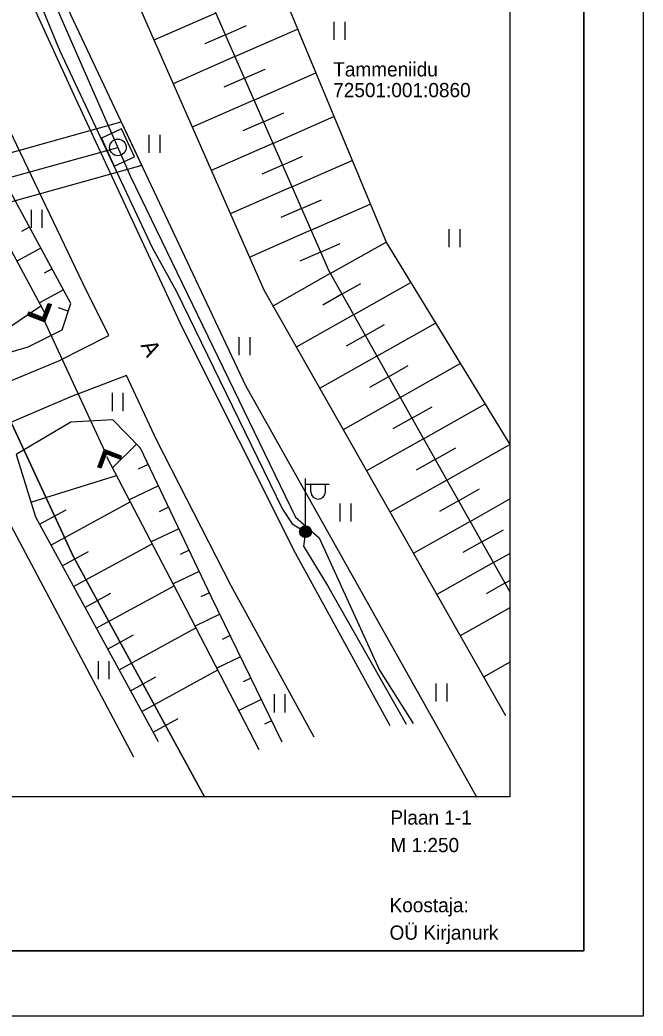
# Model space of a CAD drawing. Extents: x 533290.5 to 533343, y 6581488.2 to 6581562.4.
# Drawn here: x 533316.74 to 533343.03, y 6581488.17 to 6581530.19 of the extents above; entities that cross this region are included whole.
import ezdxf

# ---------------------------------------------------------------- set-up
doc = ezdxf.new("R2010")
doc.units = 0
for name, color, linetype in [('HALJASTUS', 7, 'Continuous'), ('KASUTUSALA', 7, 'Continuous'), ('MPKAABEL', 7, 'Continuous'), ('PIIR', 7, 'Continuous'), ('POST', 7, 'Continuous'), ('PR_SIDE', 7, 'Continuous'), ('RELJEEF', 7, 'Continuous'), ('SITRASS', 7, 'Continuous'), ('TEE', 7, 'Continuous'), ('TRUUP', 7, 'Continuous'), ('VORMISTUS', 7, 'Continuous')]:
    doc.layers.add(name, color=color, linetype=linetype)

msp = doc.modelspace()

# ---------------------------------------------------------------- linework, layer by layer
at = {"layer": 'HALJASTUS'}
for p, q in [((533329.989, 6581530.114), (533329.989, 6581529.353)), ((533330.444, 6581530.114), (533330.444, 6581529.353)), ((533322.182, 6581525.342), (533322.182, 6581524.581)), ((533322.637, 6581525.342), (533322.637, 6581524.581)), ((533317.213, 6581522.185), (533317.213, 6581521.424)), ((533317.668, 6581522.185), (533317.668, 6581521.424)), ((533334.841, 6581521.373), (533334.841, 6581520.611)), ((533335.297, 6581521.373), (533335.297, 6581520.611)), ((533325.98, 6581516.812), (533325.98, 6581516.051)), ((533326.435, 6581516.812), (533326.435, 6581516.051)), ((533320.631, 6581514.458), (533320.631, 6581513.697)), ((533321.086, 6581514.458), (533321.086, 6581513.697)), ((533330.242, 6581509.802), (533330.242, 6581509.041)), ((533330.697, 6581509.802), (533330.697, 6581509.041)), ((533320.04, 6581503.14), (533320.04, 6581502.379)), ((533320.495, 6581503.14), (533320.495, 6581502.379)), ((533334.293, 6581502.201), (533334.293, 6581501.44)), ((533334.748, 6581502.201), (533334.748, 6581501.44)), ((533327.467, 6581501.747), (533327.467, 6581500.986)), ((533327.922, 6581501.747), (533327.922, 6581500.986))]:
    msp.add_line(p, q, dxfattribs=at)
at = {"layer": 'KASUTUSALA'}
msp.add_lwpolyline([(533320.604, 6581525.778), (533321.014, 6581525.892), (533321.88, 6581524.058), (533312.538, 6581521.458), (533311.685, 6581523.295)], close=True, dxfattribs=at)
at = {"layer": 'MPKAABEL'}
msp.add_lwpolyline([(533309.585, 6581549.925), (533311.184, 6581545.697), (533315.768, 6581535.104), (533317.532, 6581531.021), (533318.413, 6581528.914), (533322.317, 6581520.59), (533323.335, 6581518.773), (533327.821, 6581509.555), (533328.223, 6581508.944), (533328.79, 6581508.605), (533328.705, 6581507.998), (533329.72, 6581506.331), (533333.034, 6581500.482)], dxfattribs=at)
at = {"layer": 'PIIR'}
for points in [[(533324.524, 6581497.425), (533319, 6581507.54), (533311.52, 6581523.65), (533301.8, 6581547.63), (533300.925, 6581549.925)], [(533300.925, 6581549.925), (533301.8, 6581547.63), (533311.52, 6581523.65), (533319, 6581507.54), (533324.524, 6581497.425)], [(533310.517, 6581549.925), (533314.39, 6581540.11), (533318.28, 6581531.69), (533326.26, 6581514.77), (533336.001, 6581497.425)], [(533337.407, 6581540.101), (533324.47, 6581534.41), (533318.28, 6581531.69), (533326.26, 6581514.77), (533336.001, 6581497.425)]]:
    msp.add_lwpolyline(points, dxfattribs=at)
at = {"layer": 'POST'}
for p, q in [((533328.79, 6581508.855), (533328.79, 6581510.855)), ((533328.79, 6581510.605), (533329.79, 6581510.605)), ((533329.017, 6581510.284), (533329.017, 6581510.605)), ((533329.63, 6581510.284), (533329.63, 6581510.605)), ((533328.79, 6581508.605), (533328.79, 6581508.605))]:
    msp.add_line(p, q, dxfattribs=at)
for radius in [0.25, 0.225, 0.2, 0.175, 0.15, 0.125, 0.1, 0.075, 0.05, 0.025]:
    msp.add_circle((533328.79, 6581508.605), radius, dxfattribs=at)
msp.add_arc((533329.323, 6581510.284), 0.306, 180, 0, dxfattribs=at)
at = {"layer": 'PR_SIDE'}
msp.add_line((533296.157, 6581517.936), (533320.872, 6581524.815), dxfattribs=at)
msp.add_lwpolyline([(533321.567, 6581524.419), (533321.023, 6581525.6), (533320.178, 6581525.212), (533320.722, 6581524.031)], close=True, dxfattribs=at)
msp.add_circle((533320.872, 6581524.815), 0.35, dxfattribs=at)
at = {"layer": 'RELJEEF'}
for p, q in [((533325.005, 6581530.479), (533322.395, 6581529.334)), ((533325.407, 6581529.563), (533326.296, 6581529.952)), ((533325.808, 6581528.647), (533328.457, 6581529.808)), ((533325.407, 6581529.563), (533324.537, 6581529.181)), ((533325.808, 6581528.647), (533323.199, 6581527.503)), ((533326.21, 6581527.731), (533325.34, 6581527.35)), ((533326.21, 6581527.731), (533327.086, 6581528.115)), ((533326.611, 6581526.815), (533329.223, 6581527.96)), ((533326.611, 6581526.815), (533324.004, 6581525.672)), ((533327.013, 6581525.899), (533327.877, 6581526.278)), ((533327.414, 6581524.983), (533329.99, 6581526.113)), ((533327.013, 6581525.899), (533326.144, 6581525.519)), ((533327.414, 6581524.983), (533324.809, 6581523.841)), ((533327.816, 6581524.068), (533328.668, 6581524.441)), ((533327.816, 6581524.068), (533326.947, 6581523.687)), ((533328.217, 6581523.152), (533330.757, 6581524.265)), ((533328.217, 6581523.152), (533325.613, 6581522.01)), ((533328.618, 6581522.236), (533327.751, 6581521.856)), ((533328.618, 6581522.236), (533329.459, 6581522.604)), ((533329.02, 6581521.32), (533331.523, 6581522.417)), ((533317.143, 6581521.447), (533316.807, 6581521.264)), ((533329.02, 6581521.32), (533326.418, 6581520.179)), ((533317.62, 6581520.568), (533316.61, 6581520.019)), ((533329.421, 6581520.404), (533330.25, 6581520.767)), ((533329.835, 6581519.494), (533332.186, 6581520.821)), ((533329.421, 6581520.404), (533328.554, 6581520.024)), ((533318.097, 6581519.689), (533317.759, 6581519.505)), ((533329.835, 6581519.494), (533327.408, 6581518.125)), ((533330.326, 6581518.623), (533331.119, 6581519.07)), ((533330.818, 6581517.752), (533333.226, 6581519.111)), ((533318.574, 6581518.81), (533317.558, 6581518.259)), ((533330.326, 6581518.623), (533329.518, 6581518.167)), ((533314.825, 6581516.252), (533317.623, 6581518.137)), ((533318.778, 6581517.906), (533318.362, 6581518.042)), ((533330.818, 6581517.752), (533328.396, 6581516.386)), ((533331.309, 6581516.881), (533332.122, 6581517.34)), ((533331.8, 6581516.01), (533334.271, 6581517.404)), ((533331.309, 6581516.881), (533330.503, 6581516.426)), ((533331.8, 6581516.01), (533329.384, 6581514.647)), ((533332.292, 6581515.139), (533333.126, 6581515.61)), ((533332.783, 6581514.268), (533335.316, 6581515.698)), ((533332.292, 6581515.139), (533331.487, 6581514.686)), ((533332.783, 6581514.268), (533330.372, 6581512.908)), ((533333.274, 6581513.398), (533334.129, 6581513.88)), ((533333.766, 6581512.527), (533336.361, 6581513.991)), ((533333.274, 6581513.398), (533332.472, 6581512.945)), ((533321.661, 6581512.301), (533320.644, 6581511.304)), ((533333.766, 6581512.527), (533331.36, 6581511.169)), ((533334.748, 6581510.785), (533337.406, 6581512.284)), ((533334.257, 6581511.656), (533335.133, 6581512.15)), ((533322.154, 6581511.442), (533321.732, 6581511.241)), ((533334.257, 6581511.656), (533333.456, 6581511.204)), ((533317.202, 6581509.848), (533320.818, 6581510.97)), ((533322.584, 6581510.54), (533321.35, 6581509.952)), ((533334.748, 6581510.785), (533332.348, 6581509.43)), ((533335.24, 6581509.914), (533336.136, 6581510.419)), ((533318.043, 6581508.043), (533321.391, 6581509.872)), ((533323.014, 6581509.637), (533322.613, 6581509.446)), ((533335.24, 6581509.914), (533334.441, 6581509.463)), ((533335.731, 6581509.043), (533337.407, 6581509.988)), ((533317.564, 6581508.921), (533318.685, 6581509.534)), ((533335.731, 6581509.043), (533333.336, 6581507.691)), ((533323.443, 6581508.734), (533322.276, 6581508.178)), ((533336.223, 6581508.172), (533337.14, 6581508.689)), ((533319.002, 6581506.288), (533322.317, 6581508.099)), ((533336.223, 6581508.172), (533335.425, 6581507.722)), ((533318.523, 6581507.166), (533319.633, 6581507.772)), ((533323.873, 6581507.831), (533323.495, 6581507.651)), ((533336.714, 6581507.301), (533337.407, 6581507.692)), ((533336.714, 6581507.301), (533334.324, 6581505.953)), ((533324.303, 6581506.928), (533323.202, 6581506.404)), ((533319.961, 6581504.533), (533323.242, 6581506.326)), ((533337.205, 6581506.43), (533336.409, 6581505.981)), ((533337.205, 6581506.43), (533337.407, 6581506.544)), ((533319.482, 6581505.411), (533320.581, 6581506.011)), ((533324.733, 6581506.025), (533324.377, 6581505.855)), ((533325.169, 6581505.125), (533324.131, 6581504.619)), ((533337.407, 6581505.396), (533335.312, 6581504.214)), ((533320.44, 6581503.655), (533321.529, 6581504.25)), ((533320.92, 6581502.778), (533324.166, 6581504.551)), ((533325.607, 6581504.226), (533325.269, 6581504.061)), ((533337.407, 6581504.247), (533337.394, 6581504.24)), ((533326.046, 6581503.327), (533325.053, 6581502.843)), ((533337.407, 6581503.099), (533336.3, 6581502.475)), ((533321.399, 6581501.9), (533322.475, 6581502.488)), ((533321.879, 6581501.023), (533325.088, 6581502.776)), ((533326.484, 6581502.429), (533326.161, 6581502.271)), ((533326.922, 6581501.53), (533325.975, 6581501.068)), ((533322.358, 6581500.145), (533323.422, 6581500.726)), ((533327.36, 6581500.631), (533327.052, 6581500.481))]:
    msp.add_line(p, q, dxfattribs=at)
for points in [[(533313.894, 6581549.925), (533319.924, 6581534.957), (533327.024, 6581518.802), (533337.222, 6581500.851)], [(533317.44, 6581549.925), (533322.824, 6581535.454), (533329.77, 6581519.61), (533337.407, 6581506.072)], [(533320.813, 6581549.925), (533325.642, 6581536.592), (533332.201, 6581520.786), (533337.407, 6581512.283)], [(533301.723, 6581543.178), (533305.883, 6581533.554), (533310.992, 6581522.492), (533312.743, 6581519.341), (533315.111, 6581515.828), (533317.088, 6581516.41), (533318.52, 6581517.115), (533318.885, 6581518.236), (533315.236, 6581524.96), (533309.937, 6581536.665), (533305.583, 6581547.162)], [(533317.816, 6581517.779), (533314.186, 6581524.519), (533308.956, 6581536.213), (533304.785, 6581546.815)], [(533327.799, 6581499.732), (533324.818, 6581505.846), (533321.825, 6581512.134), (533320.659, 6581513.322), (533318.883, 6581513.228), (533316.576, 6581511.865), (533317.392, 6581509.235), (533322.569, 6581499.759)], [(533326.836, 6581499.41), (533323.749, 6581505.354), (533320.405, 6581511.761)]]:
    msp.add_lwpolyline(points, dxfattribs=at)
at = {"layer": 'SITRASS'}
msp.add_lwpolyline([(533310.167, 6581549.925), (533314.701, 6581538.877), (533321.41, 6581523.582), (533328.373, 6581509.225), (533329.36, 6581508.341), (533331.911, 6581502.769), (533333.333, 6581500.509)], dxfattribs=at)
at = {"layer": 'TEE'}
for points in [[(533332.365, 6581500.423), (533328.37, 6581507.695), (533323.599, 6581517.205), (533319.091, 6581526.86), (533313.759, 6581538.502), (533308.885, 6581549.596)], [(533300.834, 6581542.715), (533304.915, 6581533.103), (533309.953, 6581521.952), (533312.545, 6581516.498), (533313.78, 6581513.945), (533314.812, 6581514.331), (533318.385, 6581515.808), (533320.487, 6581516.887), (533319.399, 6581519.093), (533316.302, 6581525.558), (533311.019, 6581537.113), (533306.407, 6581547.637)], [(533329.158, 6581499.94), (533325.649, 6581506.325), (533322.502, 6581512.484), (533321.231, 6581515.194), (533318.912, 6581514.304), (533315.616, 6581512.897), (533314.671, 6581512.318), (533316.354, 6581508.865), (533321.528, 6581499.114)]]:
    msp.add_lwpolyline(points, dxfattribs=at)
at = {"layer": 'TRUUP'}
for p, q in [((533317.706, 6581517.646), (533317.937, 6581518.238)), ((533317.747, 6581517.554), (533318.003, 6581518.212)), ((533317.787, 6581517.461), (533318.07, 6581518.187)), ((533317.864, 6581518.05), (533317.97, 6581517.932)), ((533317.874, 6581518.077), (533317.981, 6581517.958)), ((533317.884, 6581518.103), (533317.991, 6581517.984)), ((533317.894, 6581518.129), (533318.001, 6581518.01)), ((533317.904, 6581518.155), (533318.011, 6581518.036)), ((533317.915, 6581518.181), (533318.021, 6581518.062)), ((533317.925, 6581518.207), (533318.031, 6581518.088)), ((533317.935, 6581518.233), (533318.042, 6581518.114)), ((533317.937, 6581518.238), (533318.07, 6581518.187)), ((533317.978, 6581518.222), (533318.052, 6581518.141)), ((533318.03, 6581518.202), (533318.062, 6581518.167)), ((533317.114, 6581517.877), (533317.062, 6581517.744)), ((533317.062, 6581517.744), (533317.787, 6581517.461)), ((533317.073, 6581517.771), (533317.116, 6581517.723)), ((533317.083, 6581517.797), (533317.168, 6581517.703)), ((533317.088, 6581517.81), (533317.747, 6581517.554)), ((533317.093, 6581517.823), (533317.22, 6581517.682)), ((533317.103, 6581517.85), (533317.272, 6581517.662)), ((533317.113, 6581517.876), (533317.323, 6581517.642)), ((533317.114, 6581517.877), (533317.706, 6581517.646)), ((533317.163, 6581517.857), (533317.375, 6581517.622)), ((533317.215, 6581517.837), (533317.427, 6581517.602)), ((533317.267, 6581517.817), (533317.479, 6581517.582)), ((533317.319, 6581517.797), (533317.53, 6581517.561)), ((533317.371, 6581517.776), (533317.582, 6581517.541)), ((533317.422, 6581517.756), (533317.634, 6581517.521)), ((533317.474, 6581517.736), (533317.686, 6581517.501)), ((533317.526, 6581517.716), (533317.737, 6581517.481)), ((533317.578, 6581517.696), (533317.787, 6581517.462)), ((533317.629, 6581517.676), (533317.798, 6581517.488)), ((533317.681, 6581517.655), (533317.808, 6581517.515)), ((533317.711, 6581517.659), (533317.818, 6581517.541)), ((533317.722, 6581517.685), (533317.828, 6581517.567)), ((533317.732, 6581517.711), (533317.838, 6581517.593)), ((533317.742, 6581517.737), (533317.848, 6581517.619)), ((533317.752, 6581517.764), (533317.859, 6581517.645)), ((533317.762, 6581517.79), (533317.869, 6581517.671)), ((533317.772, 6581517.816), (533317.879, 6581517.697)), ((533317.783, 6581517.842), (533317.889, 6581517.723)), ((533317.793, 6581517.868), (533317.899, 6581517.749)), ((533317.803, 6581517.894), (533317.909, 6581517.775)), ((533317.813, 6581517.92), (533317.92, 6581517.801)), ((533317.823, 6581517.946), (533317.93, 6581517.828)), ((533317.833, 6581517.972), (533317.94, 6581517.854)), ((533317.843, 6581517.998), (533317.95, 6581517.88)), ((533317.854, 6581518.024), (533317.96, 6581517.906)), ((533320.34, 6581511.979), (533317.747, 6581517.554)), ((533320.299, 6581512.071), (533320.02, 6581511.344)), ((533320.34, 6581511.979), (533320.087, 6581511.319)), ((533320.381, 6581511.887), (533320.153, 6581511.293)), ((533320.276, 6581511.612), (533320.168, 6581511.73)), ((533320.286, 6581511.638), (533320.178, 6581511.756)), ((533320.296, 6581511.664), (533320.188, 6581511.782)), ((533320.306, 6581511.69), (533320.199, 6581511.808)), ((533320.316, 6581511.717), (533320.209, 6581511.835)), ((533320.326, 6581511.743), (533320.219, 6581511.861)), ((533320.336, 6581511.769), (533320.229, 6581511.887)), ((533320.346, 6581511.795), (533320.239, 6581511.913)), ((533320.356, 6581511.821), (533320.249, 6581511.939)), ((533320.366, 6581511.847), (533320.259, 6581511.965)), ((533320.376, 6581511.873), (533320.269, 6581511.991)), ((533320.406, 6581511.877), (533320.279, 6581512.017)), ((533320.458, 6581511.857), (533320.289, 6581512.044)), ((533321.026, 6581511.791), (533320.299, 6581512.071)), ((533320.51, 6581511.837), (533320.299, 6581512.07)), ((533321, 6581511.725), (533320.34, 6581511.979)), ((533320.562, 6581511.817), (533320.349, 6581512.052)), ((533320.975, 6581511.659), (533320.381, 6581511.887)), ((533320.614, 6581511.797), (533320.401, 6581512.032)), ((533320.665, 6581511.777), (533320.453, 6581512.012)), ((533320.717, 6581511.758), (533320.505, 6581511.992)), ((533320.769, 6581511.738), (533320.557, 6581511.972)), ((533320.821, 6581511.718), (533320.608, 6581511.952)), ((533320.873, 6581511.698), (533320.66, 6581511.932)), ((533320.925, 6581511.678), (533320.712, 6581511.912)), ((533320.975, 6581511.66), (533320.764, 6581511.892)), ((533320.985, 6581511.686), (533320.816, 6581511.872)), ((533320.995, 6581511.712), (533320.868, 6581511.852)), ((533321.005, 6581511.738), (533320.92, 6581511.832)), ((533321.015, 6581511.764), (533320.971, 6581511.812)), ((533320.975, 6581511.659), (533321.026, 6581511.791)), ((533320.153, 6581511.293), (533320.02, 6581511.344)), ((533320.06, 6581511.329), (533320.028, 6581511.364)), ((533320.111, 6581511.309), (533320.038, 6581511.39)), ((533320.155, 6581511.298), (533320.048, 6581511.416)), ((533320.165, 6581511.325), (533320.058, 6581511.443)), ((533320.175, 6581511.351), (533320.068, 6581511.469)), ((533320.185, 6581511.377), (533320.078, 6581511.495)), ((533320.195, 6581511.403), (533320.088, 6581511.521)), ((533320.205, 6581511.429), (533320.098, 6581511.547)), ((533320.215, 6581511.455), (533320.108, 6581511.573)), ((533320.225, 6581511.481), (533320.118, 6581511.599)), ((533320.235, 6581511.507), (533320.128, 6581511.626)), ((533320.245, 6581511.534), (533320.138, 6581511.652)), ((533320.255, 6581511.56), (533320.148, 6581511.678)), ((533320.265, 6581511.586), (533320.158, 6581511.704))]:
    msp.add_line(p, q, dxfattribs=at)
at = {"layer": 'VORMISTUS'}
for points in [[(533290.532, 6581562.425), (533343.032, 6581562.425), (533343.032, 6581488.175), (533290.532, 6581488.175)], [(533293.032, 6581490.925), (533340.532, 6581490.925), (533340.532, 6581559.675), (533293.032, 6581559.675)], [(533293.032, 6581559.675), (533340.532, 6581559.675), (533340.532, 6581490.925), (533293.032, 6581490.925)], [(533337.407, 6581497.425), (533296.157, 6581497.425), (533296.157, 6581549.925), (533337.407, 6581549.925)]]:
    msp.add_lwpolyline(points, close=True, dxfattribs=at)

# ---------------------------------------------------------------- texts
at = {"layer": 'PIIR'}
for s, p in [('Tammeniidu', (533329.957, 6581527.809)), ('72501:001:0860', (533329.957, 6581526.934))]:
    msp.add_text(s, height=0.6, dxfattribs=at).set_placement(p)
at = {"layer": 'TEE'}
msp.add_text('A', height=0.7, rotation=297.3734, dxfattribs=at).set_placement((533321.816, 6581516.466))
at = {"layer": 'VORMISTUS'}
for s, p in [('Plaan 1-1', (533332.372, 6581496.249)), ('M 1:250', (533332.372, 6581495.089)), ('Koostaja:', (533332.334, 6581492.555)), ('OÜ Kirjanurk', (533332.334, 6581491.396))]:
    msp.add_text(s, height=0.6, dxfattribs=at).set_placement(p)

doc.saveas('drawing.dxf')
